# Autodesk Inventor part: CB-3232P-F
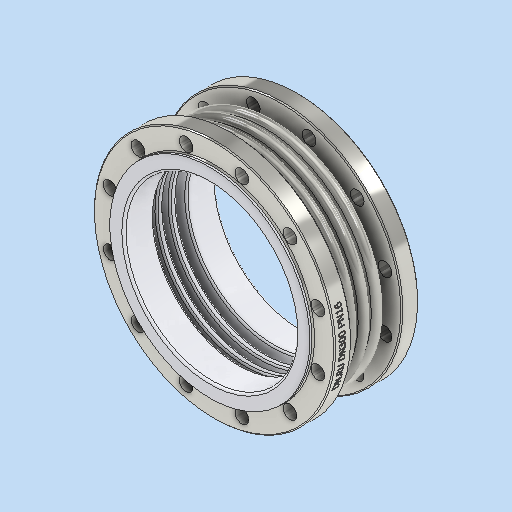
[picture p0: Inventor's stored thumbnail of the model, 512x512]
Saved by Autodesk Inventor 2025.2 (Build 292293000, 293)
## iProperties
Company: DN.RU
Created: 2026-04
Part Number: CB-3232P-F
Material: Типовые
Document SubType Name: Modeling
Designer: DN.RU
Density: 6.33917 g/cm^3
Appearance: По умолчанию
Description: D140-02146
Mass: 40900 g
Surface Area: 13558.3 cm^2
Volume: 6451.95 cm^3
Author: DN.RU
Title: Компенсатор сильфонный осевой DN.ru Ду300 Ру16
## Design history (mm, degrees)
sketch "Эскиз1"
  geometry: L1 (0, 0)-(0, -80); L2 (173.75, -80)-(173.75, 0); L3 (173.75, 0)-(0, 0); L4 (173.75, 0)-(173.75, 0); L5 (143.75, 0)-(203.75, 0); L6 (143.75, -9)-(203.75, -9); L7 (203.75, 9)-(143.75, 9); L8 (203.75, -6)-(143.75, -6); L9 (143.75, 6)-(203.75, 6); L10 (203.75, -16)-(143.75, -16); L11 (143.75, -19)-(203.75, -19); L12 (143.75, -25)-(203.75, -25); L13 (143.75, -34)-(203.75, -34); L14 (203.75, -31)-(143.75, -31); L15 (0, -80)-(173.75, -80); L16 (173.75, -80)-(163.75, -80); L17 (163.75, -80)-(163.75, -31); L18 (173.75, -19)-(170.75, -19); L19 (170.75, -19)-(170.75, -6); L20 (173.75, 6)-(170.75, 6); L21 (170.75, 6)-(170.75, 0); L22 (0, -80)-(0, -48); L23 (0, -48)-(230, -48); L24 (230, -48)-(230, -80); L25 (230, -80)-(0, -80); L26 (173.75, -48)-(173.75, -66); L27 (173.75, -66)-(178.75, -66); L28 (178.75, -66)-(178.75, -48); L29 (178.75, -48)-(173.75, -48); L30 (173.75, 0)-(212.75, 0); A1 r 9 centre (143.75, 0) between (143.75, 9) and (143.75, -9); A2 r 9 centre (203.75, 0) between (203.75, -9) and (203.75, 9); A3 r 6 centre (143.75, 0) between (143.75, 6) and (143.75, -6); A4 r 6 centre (203.75, 0) between (203.75, -6) and (203.75, 6); A5 r 6 centre (143.75, -25) between (143.75, -19) and (143.75, -31); A6 r 9 centre (143.75, -25) between (143.75, -16) and (143.75, -34); A7 r 6 centre (203.75, -25) between (203.75, -31) and (203.75, -19); A8 r 9 centre (203.75, -25) between (203.75, -34) and (203.75, -16); 20 further points
  constraints: 64 end point, 17 point on circle, 14 point on line, 8 centre point, 7 parallel, 5 perpendicular, 4 tangent, 3 midpoint, 2 vertical, 1 horizontal, 25 other
  dimensions: "d0" = 80 distance of L1.start L1.end; "d3" = 0 distance of L2.end L4.end; "d4" = 30 distance of L4.end L5.end; "d5" = 18 diameter of A2; "d6" = 3 distance between parallel lines of L6 L8; "d9" = 25 distance of L4.end point (173.75, -25); "d18" = 3 distance of L18.start L18.end; "d19" = 3 distance of L20.start L20.end; "d27" = 163.75 distance between parallel lines of L1 L17; "d28" = 10 distance between parallel lines of L2 L17; "d29" = 32 distance of L1.end L22.end; "d30" = 230 distance of L22.end L23.end; "d31" = 18 distance of L26.start L26.end; "d32" = 5 distance of L27.end L26.end
revolve "Вращение1" sketch "Эскиз1" stored, may be unused: angle "d20" = 360 deg
sketch "Эскиз3" dims "d33" = 410
  geometry: L1 (0, 0)-(74.331, 19.917); L2 (0, 0)-(76.954, 0); C1 r 13 at (198.015, 53.058); C2 r 13 at (144.957, 144.957); C3 r 13 at (53.058, 198.015); C4 r 13 at (-53.058, 198.015); C5 r 163.75 at (0, 0) reference; C6 r 187.5 at (0, 0); C7 r 230 at (0, 0) reference; C8 r 13 at (-144.957, 144.957); C9 r 13 at (-198.015, 53.058); C10 r 13 at (-198.015, -53.058); C11 r 13 at (-144.957, -144.957); C12 r 13 at (-53.058, -198.015); C13 r 13 at (53.058, -198.015); C14 r 13 at (144.957, -144.957); C15 r 13 at (198.015, -53.058); 1 further point
  constraints: 13 centre point, 4 end point, 2 coincident, 1 equal length, 1 horizontal, 1 point on line, 28 other
  dimensions: "d34" = 15 deg angle of L2 L1; "d35" = 26 diameter of C1; "d38" = 360 deg dimension on point (0, 0) C1.centre (derived); "d40" = 375 diameter of C6
  node "Эскиз — круговой массив1" dims "d38" = 360 deg (derived)
extrude "Выдавливание1" cut sketch "Эскиз3" stored distance "d41" = 10; taper "d42" = 0 deg
extrude "Выдавливание2" join sketch "Эскиз3" distance "d43" = 4; taper "d44" = 0 deg
chamfer "Фаска2" distance "d45" = 4; stored, may be unused: second distance "d46" = 2, angle "d47" = 45 deg
chamfer "Фаска3" distance "d48" = 2; stored, may be unused: second distance "d49" = 2, angle "d50" = 45 deg
mirror "Зеркальное отражение2"
fillet "Сопряжение2" dims "d51" = 3
node "РабПлоскость2"
sketch "Эскиз4"
  geometry: L1 (-79.676, 7.524)-(96.959, 7.524); L2 (96.959, 7.524)-(96.959, -33.595); L3 (96.959, -33.595)-(-79.676, -33.595); L4 (-79.676, -33.595)-(-79.676, 7.524); 1 further point
  constraints: 2 other
feature "Рельеф2" sketch "Эскиз4" dims "d3" = 0, "d52" = 0.1, "d53" = 0
sketch "Эскиз5"
  geometry: C1 r 163.75 at (0, 0) reference; C2 r 190.75 at (0, 0); 1 further point
  constraints: 1 centre point
  dimensions: "d54" = 27 radial gap between concentric circles of C1 C2
extrude "Выдавливание3" join sketch "Эскиз5" distance "d55" = 4; taper "d56" = 0 deg
fillet "Сопряжение3" dims "d57" = 4
mirror "Зеркальное отражение3"
feature "Ɋ耀Ɍ耀Ɏ耀ɐ耀ɒ耀ɔ耀ɖ耀ɘ耀" dims "d0" = 80, "d3" = 0, "d4" = 30, "d5" = 18, "d6" = 3, "d7" = 20, "d9" = 25, "d10" = 10, "d12" = 10, "d18" = 3, "d19" = 3, "d20" = 360 deg, "d27" = 163.75, "d28" = 10, "d29" = 32, "d30" = 230, "d31" = 18, "d32" = 5, "d33" = 410, "d34" = 15 deg, "d35" = 26, "d36" = 120, "d38" = 360 deg (derived), "d40" = 375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
node "Твердое тело1"
node "Эскиз — прямоугольный массив1" dims "d9" = 25, "d12" = 10
